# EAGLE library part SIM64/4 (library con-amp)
AMP connector
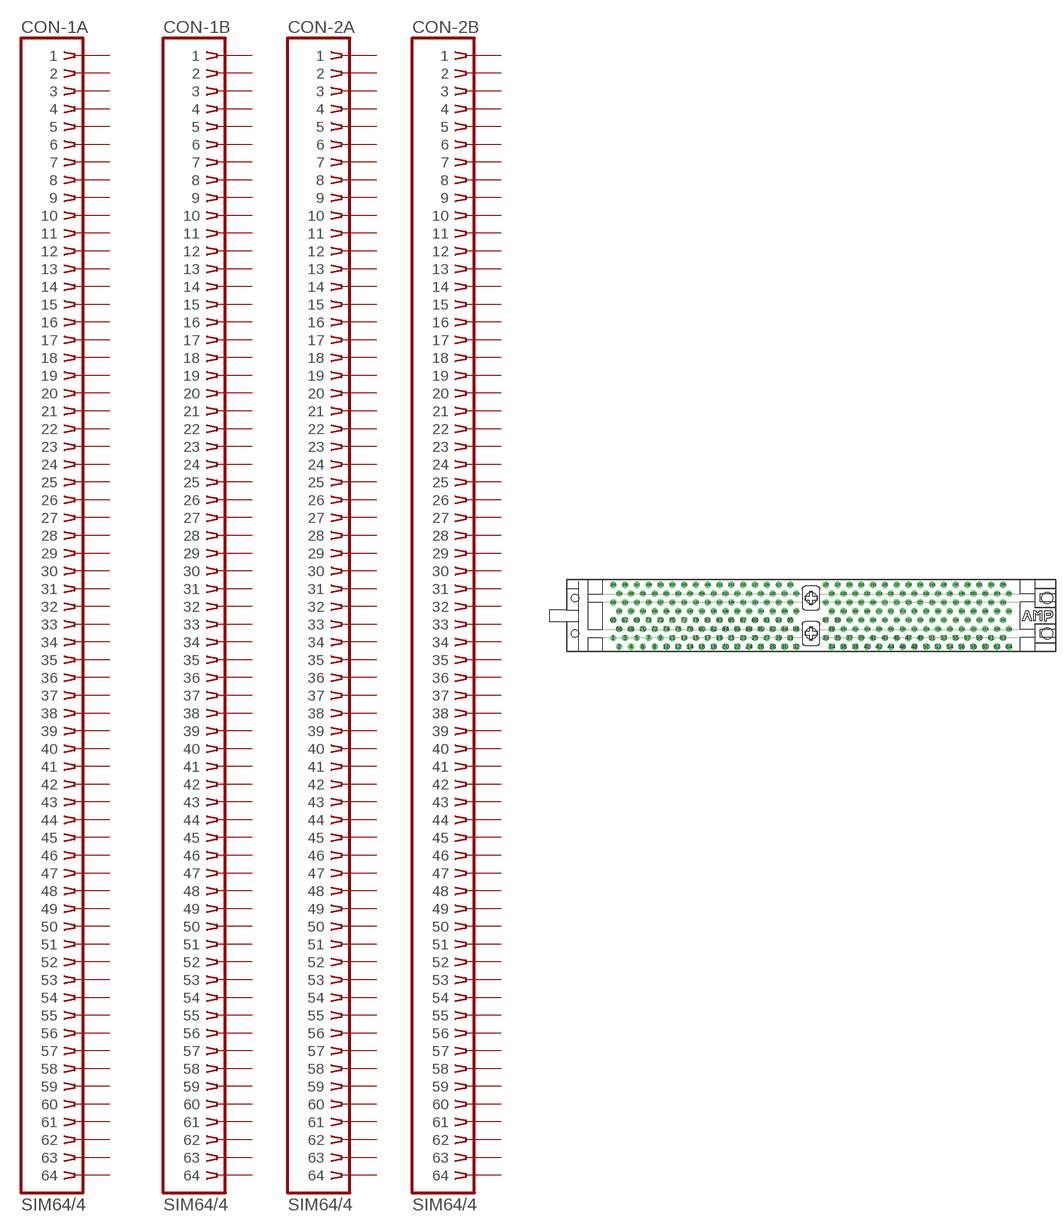
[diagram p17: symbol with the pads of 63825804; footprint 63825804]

Designator prefix CON; gates -1A=SIMM64 -1B=SIMM64 -2A=SIMM64 -2B=SIMM64

## SIM64/4 (OC_FARNELL: unknown; OC_NEWARK: unknown)  [63825804]
1  -1A:1  pas
2  -1A:2  pas
3  -1A:3  pas
4  -1A:4  pas
5  -1A:5  pas
6  -1A:6  pas
7  -1A:7  pas
8  -1A:8  pas
9  -1A:9  pas
10  -1A:10  pas
11  -1A:11  pas
12  -1A:12  pas
13  -1A:13  pas
14  -1A:14  pas
15  -1A:15  pas
16  -1A:16  pas
17  -1A:17  pas
18  -1A:18  pas
19  -1A:19  pas
20  -1A:20  pas
21  -1A:21  pas
22  -1A:22  pas
23  -1A:23  pas
24  -1A:24  pas
25  -1A:25  pas
26  -1A:26  pas
27  -1A:27  pas
28  -1A:28  pas
29  -1A:29  pas
30  -1A:30  pas
31  -1A:31  pas
32  -1A:32  pas
33  -1A:33  pas
34  -1A:34  pas
35  -1A:35  pas
36  -1A:36  pas
37  -1A:37  pas
38  -1A:38  pas
39  -1A:39  pas
40  -1A:40  pas
41  -1A:41  pas
42  -1A:42  pas
43  -1A:43  pas
44  -1A:44  pas
45  -1A:45  pas
46  -1A:46  pas
47  -1A:47  pas
48  -1A:48  pas
49  -1A:49  pas
50  -1A:50  pas
51  -1A:51  pas
52  -1A:52  pas
53  -1A:53  pas
54  -1A:54  pas
55  -1A:55  pas
56  -1A:56  pas
57  -1A:57  pas
58  -1A:58  pas
59  -1A:59  pas
60  -1A:60  pas
61  -1A:61  pas
62  -1A:62  pas
63  -1A:63  pas
64  -1A:64  pas
65  -1B:1  pas
66  -1B:2  pas
67  -1B:3  pas
68  -1B:4  pas
69  -1B:5  pas
70  -1B:6  pas
71  -1B:7  pas
72  -1B:8  pas
73  -1B:9  pas
74  -1B:10  pas
75  -1B:11  pas
76  -1B:12  pas
77  -1B:13  pas
78  -1B:14  pas
79  -1B:15  pas
80  -1B:16  pas
81  -1B:17  pas
82  -1B:18  pas
83  -1B:19  pas
84  -1B:20  pas
85  -1B:21  pas
86  -1B:22  pas
87  -1B:23  pas
88  -1B:24  pas
89  -1B:25  pas
90  -1B:26  pas
91  -1B:27  pas
92  -1B:28  pas
93  -1B:29  pas
94  -1B:30  pas
95  -1B:31  pas
96  -1B:32  pas
97  -1B:33  pas
98  -1B:34  pas
99  -1B:35  pas
100  -1B:36  pas
101  -1B:37  pas
102  -1B:38  pas
103  -1B:39  pas
104  -1B:40  pas
105  -1B:41  pas
106  -1B:42  pas
107  -1B:43  pas
108  -1B:44  pas
109  -1B:45  pas
110  -1B:46  pas
111  -1B:47  pas
112  -1B:48  pas
113  -1B:49  pas
114  -1B:50  pas
115  -1B:51  pas
116  -1B:52  pas
117  -1B:53  pas
118  -1B:54  pas
119  -1B:55  pas
120  -1B:56  pas
121  -1B:57  pas
122  -1B:58  pas
123  -1B:59  pas
124  -1B:60  pas
125  -1B:61  pas
126  -1B:62  pas
127  -1B:63  pas
128  -1B:64  pas
129  -2A:1  pas
130  -2A:2  pas
131  -2A:3  pas
132  -2A:4  pas
133  -2A:5  pas
134  -2A:6  pas
135  -2A:7  pas
136  -2A:8  pas
137  -2A:9  pas
138  -2A:10  pas
139  -2A:11  pas
140  -2A:12  pas
141  -2A:13  pas
142  -2A:14  pas
143  -2A:15  pas
144  -2A:16  pas
145  -2A:17  pas
146  -2A:18  pas
147  -2A:19  pas
148  -2A:20  pas
149  -2A:21  pas
150  -2A:22  pas
151  -2A:23  pas
152  -2A:24  pas
153  -2A:25  pas
154  -2A:26  pas
155  -2A:27  pas
156  -2A:28  pas
157  -2A:29  pas
158  -2A:30  pas
159  -2A:31  pas
160  -2A:32  pas
161  -2A:33  pas
162  -2A:34  pas
163  -2A:35  pas
164  -2A:36  pas
165  -2A:37  pas
166  -2A:38  pas
167  -2A:39  pas
168  -2A:40  pas
169  -2A:41  pas
170  -2A:42  pas
171  -2A:43  pas
172  -2A:44  pas
173  -2A:45  pas
174  -2A:46  pas
175  -2A:47  pas
176  -2A:48  pas
177  -2A:49  pas
178  -2A:50  pas
179  -2A:51  pas
180  -2A:52  pas
181  -2A:53  pas
182  -2A:54  pas
183  -2A:55  pas
184  -2A:56  pas
185  -2A:57  pas
186  -2A:58  pas
187  -2A:59  pas
188  -2A:60  pas
189  -2A:61  pas
190  -2A:62  pas
191  -2A:63  pas
192  -2A:64  pas
193  -2B:1  pas
194  -2B:2  pas
195  -2B:3  pas
196  -2B:4  pas
197  -2B:5  pas
198  -2B:6  pas
199  -2B:7  pas
200  -2B:8  pas
201  -2B:9  pas
202  -2B:10  pas
203  -2B:11  pas
204  -2B:12  pas
205  -2B:13  pas
206  -2B:14  pas
207  -2B:15  pas
208  -2B:16  pas
209  -2B:17  pas
210  -2B:18  pas
211  -2B:19  pas
212  -2B:20  pas
213  -2B:21  pas
214  -2B:22  pas
215  -2B:23  pas
216  -2B:24  pas
217  -2B:25  pas
218  -2B:26  pas
219  -2B:27  pas
220  -2B:28  pas
221  -2B:29  pas
222  -2B:30  pas
223  -2B:31  pas
224  -2B:32  pas
225  -2B:33  pas
226  -2B:34  pas
227  -2B:35  pas
228  -2B:36  pas
229  -2B:37  pas
230  -2B:38  pas
231  -2B:39  pas
232  -2B:40  pas
233  -2B:41  pas
234  -2B:42  pas
235  -2B:43  pas
236  -2B:44  pas
237  -2B:45  pas
238  -2B:46  pas
239  -2B:47  pas
240  -2B:48  pas
241  -2B:49  pas
242  -2B:50  pas
243  -2B:51  pas
244  -2B:52  pas
245  -2B:53  pas
246  -2B:54  pas
247  -2B:55  pas
248  -2B:56  pas
249  -2B:57  pas
250  -2B:58  pas
251  -2B:59  pas
252  -2B:60  pas
253  -2B:61  pas
254  -2B:62  pas
255  -2B:63  pas
256  -2B:64  pas

## Footprint 63825804 (pad centres in mm)
DIMM I Dual Read Out
drill 0.813 round: 1 -42.545,-4.763
drill 0.813 octagon: 2 -41.275,-6.668; 3 -40.005,-4.763; 4 -38.735,-6.668; 5 -37.465,-4.763; 6 -36.195,-6.668; 7 -34.925,-4.763; 8 -33.655,-6.668; 9 -32.385,-4.763; 10 -31.115,-6.668; 11 -29.845,-4.763; 12 -28.575,-6.668; 13 -27.305,-4.763; 14 -26.035,-6.668; 15 -24.765,-4.763; 16 -23.495,-6.668; 17 -22.225,-4.763; 18 -20.955,-6.668; 19 -19.685,-4.763; 20 -18.415,-6.668; 21 -17.145,-4.763; 22 -15.875,-6.668; 23 -14.605,-4.763; 24 -13.335,-6.668; 25 -12.065,-4.763; 26 -10.795,-6.668; 27 -9.525,-4.763; 28 -8.255,-6.668; 29 -6.985,-4.763; 30 -5.715,-6.668; 31 -4.445,-4.763; 32 -3.175,-6.668; 33 3.175,-4.763; 34 4.445,-6.668; 35 5.715,-4.763; 36 6.985,-6.668; 37 8.255,-4.763; 38 9.525,-6.668; 39 10.795,-4.763; 40 12.065,-6.668; 41 13.335,-4.763; 42 14.605,-6.668; 43 15.875,-4.763; 44 17.145,-6.668; 45 18.415,-4.763; 46 19.685,-6.668; 47 20.955,-4.763; 48 22.225,-6.668; 49 23.495,-4.763; 50 24.765,-6.668; 51 26.035,-4.763; 52 27.305,-6.668; 53 28.575,-4.763; 54 29.845,-6.668; 55 31.115,-4.763; 56 32.385,-6.668; 57 33.655,-4.763; 58 34.925,-6.668; 59 36.195,-4.763; 60 37.465,-6.668; 61 38.735,-4.763; 62 40.005,-6.668; 63 41.275,-4.763; 64 42.545,-6.668; 65 -42.545,-0.953; 66 -41.275,-2.857; 67 -40.005,-0.953; 68 -38.735,-2.857; 69 -37.465,-0.953; 70 -36.195,-2.857; 71 -34.925,-0.953; 72 -33.655,-2.857; 73 -32.385,-0.953; 74 -31.115,-2.857; 75 -29.845,-0.953; 76 -28.575,-2.857; 77 -27.305,-0.953; 78 -26.035,-2.857; 79 -24.765,-0.953; 80 -23.495,-2.857; 81 -22.225,-0.953; 82 -20.955,-2.857; 83 -19.685,-0.953; 84 -18.415,-2.857; 85 -17.145,-0.953; 86 -15.875,-2.857; 87 -14.605,-0.953; 88 -13.335,-2.857; 89 -12.065,-0.953; 90 -10.795,-2.857; 91 -9.525,-0.953; 92 -8.255,-2.857; 93 -6.985,-0.953; 94 -5.715,-2.857; 95 -4.445,-0.953; 96 -3.175,-2.857; 97 3.175,-0.953; 98 4.445,-2.857; 99 5.715,-0.953; 100 6.985,-2.857; 101 8.255,-0.953; 102 9.525,-2.857; 103 10.795,-0.953; 104 12.065,-2.857; 105 13.335,-0.953; 106 14.605,-2.857; 107 15.875,-0.953; 108 17.145,-2.857; 109 18.415,-0.953; 110 19.685,-2.857; 111 20.955,-0.953; 112 22.225,-2.857; 113 23.495,-0.953; 114 24.765,-2.857; 115 26.035,-0.953; 116 27.305,-2.857; 117 28.575,-0.953; 118 29.845,-2.857; 119 31.115,-0.953; 120 32.385,-2.857; 121 33.655,-0.953; 122 34.925,-2.857; 123 36.195,-0.953; 124 37.465,-2.857; 125 38.735,-0.953; 126 40.005,-2.857; 127 41.275,-0.953; 128 42.545,-2.857; 129 -42.545,2.857; 130 -41.275,0.953; 131 -40.005,2.857; 132 -38.735,0.953; 133 -37.465,2.857; 134 -36.195,0.953; 135 -34.925,2.857; 136 -33.655,0.953; 137 -32.385,2.857; 138 -31.115,0.953; 139 -29.845,2.857; 140 -28.575,0.953; 141 -27.305,2.857; 142 -26.035,0.953; 143 -24.765,2.857; 144 -23.495,0.953; 145 -22.225,2.857; 146 -20.955,0.953; 147 -19.685,2.857; 148 -18.415,0.953; 149 -17.145,2.857; 150 -15.875,0.953; 151 -14.605,2.857; 152 -13.335,0.953; 153 -12.065,2.857; 154 -10.795,0.953; 155 -9.525,2.857; 156 -8.255,0.953; 157 -6.985,2.857; 158 -5.715,0.953; 159 -4.445,2.857; 160 -3.175,0.953; 161 3.175,2.857; 162 4.445,0.953; 163 5.715,2.857; 164 6.985,0.953; 165 8.255,2.857; 166 9.525,0.953; 167 10.795,2.857; 168 12.065,0.953; 169 13.335,2.857; 170 14.605,0.953; 171 15.875,2.857; 172 17.145,0.953; 173 18.415,2.857; 174 19.685,0.953; 175 20.955,2.857; 176 22.225,0.953; 177 23.495,2.857; 178 24.765,0.953; 179 26.035,2.857; 180 27.305,0.953; 181 28.575,2.857; 182 29.845,0.953; 183 31.115,2.857; 184 32.385,0.953; 185 33.655,2.857; 186 34.925,0.953; 187 36.195,2.857; 188 37.465,0.953; 189 38.735,2.857; 190 40.005,0.953; 191 41.275,2.857; 192 42.545,0.953; 193 -42.545,6.668; 194 -41.275,4.763; 195 -40.005,6.668; 196 -38.735,4.763; 197 -37.465,6.668; 198 -36.195,4.763; 199 -34.925,6.668; 200 -33.655,4.763; 201 -32.385,6.668; 202 -31.115,4.763; 203 -29.845,6.668; 204 -28.575,4.763; 205 -27.305,6.668; 206 -26.035,4.763; 207 -24.765,6.668; 208 -23.495,4.763; 209 -22.225,6.668; 210 -20.955,4.763; 211 -19.685,6.668; 212 -18.415,4.763; 213 -17.145,6.668; 214 -15.875,4.763; 215 -14.605,6.668; 216 -13.335,4.763; 217 -12.065,6.668; 218 -10.795,4.763; 219 -9.525,6.668; 220 -8.255,4.763; 221 -6.985,6.668; 222 -5.715,4.763; 223 -4.445,6.668; 224 -3.175,4.763; 225 3.175,6.668; 226 4.445,4.763; 227 5.715,6.668; 228 6.985,4.763; 229 8.255,6.668; 230 9.525,4.763; 231 10.795,6.668; 232 12.065,4.763; 233 13.335,6.668; 234 14.605,4.763; 235 15.875,6.668; 236 17.145,4.763; 237 18.415,6.668; 238 19.685,4.763; 239 20.955,6.668; 240 22.225,4.763; 241 23.495,6.668; 242 24.765,4.763; 243 26.035,6.668; 244 27.305,4.763; 245 28.575,6.668; 246 29.845,4.763; 247 31.115,6.668; 248 32.385,4.763; 249 33.655,6.668; 250 34.925,4.763; 251 36.195,6.668; 252 37.465,4.763; 253 38.735,6.668; 254 40.005,4.763; 255 41.275,6.668; 256 42.545,4.763
hole 1.575 at -50.8,-3.81
hole 2.362 at 0,-3.81
hole 2.362 at 50.8,-3.81
hole 1.575 at -50.8,3.81
hole 2.362 at 0,3.81
hole 2.362 at 50.8,3.81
